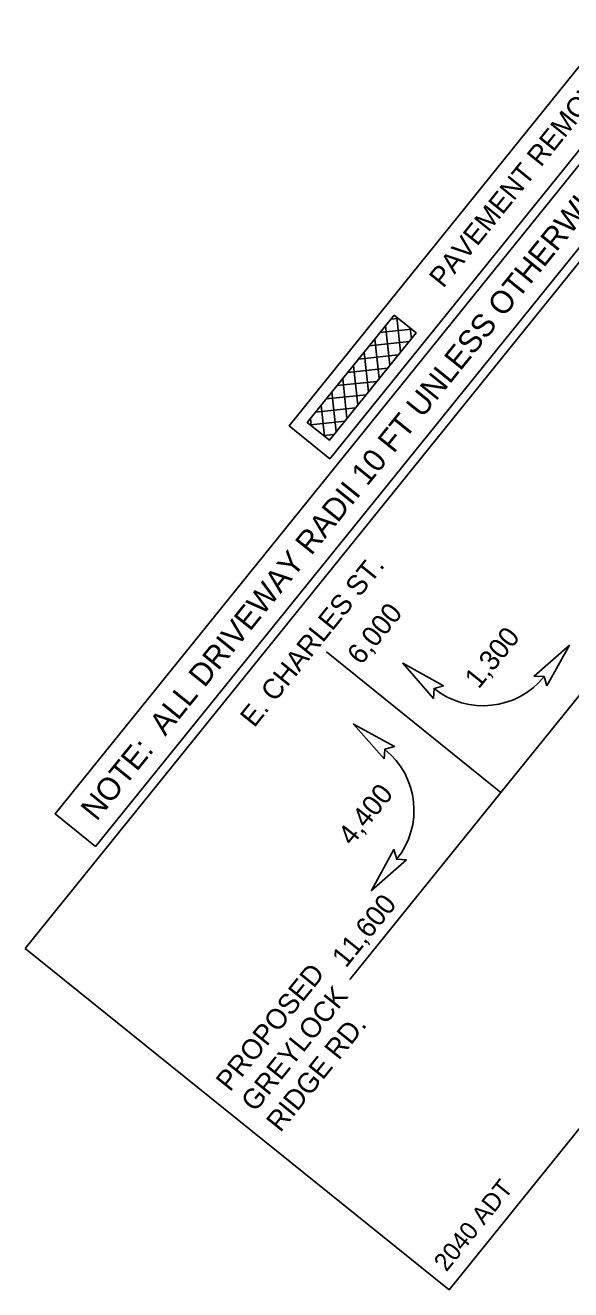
# Model space of a CAD drawing. Extents: x 1487832 to 1490056, y 498345 to 500343.
# Drawn here: x 1489252.4 to 1489387.8, y 499624 to 499938.3 of the extents above; entities that cross this region are included whole.
import ezdxf

# ---------------------------------------------------------------- set-up
doc = ezdxf.new("R2010")
doc.units = 0
for name, color, linetype in [('Prop DSN Text', 7, 'Continuous'), ('Prop Grid Mask', 7, 'Continuous'), ('Prop Hatching', 7, 'Continuous'), ('Prop Horizontal Alignment Curve and Spiral Data', 7, 'Continuous')]:
    doc.layers.add(name, color=color, linetype=linetype)

msp = doc.modelspace()

# ---------------------------------------------------------------- linework, layer by layer
at = {"layer": 'Prop DSN Text'}
for p in [(1489407.93, 499794.07), (1489327.11, 499782.51), (1489332.93, 499701.07)]:
    msp.add_line(p, (1489370.43, 499747.57), dxfattribs=at)
for points in [[(1489381.83, 499774.06), (1489387.45, 499784.16), (1489378.68, 499776.51), (1489381.17, 499776.38)], [(1489356.15, 499774.1), (1489346.05, 499779.72), (1489353.69, 499770.96), (1489353.83, 499773.45)], [(1489341.48, 499755.91), (1489333.84, 499764.59), (1489344.03, 499758.97), (1489341.63, 499758.31)], [(1489346.96, 499730.82), (1489338.28, 499723.19), (1489343.89, 499733.37), (1489344.56, 499730.97)]]:
    msp.add_lwpolyline(points, close=True, dxfattribs=at)
for centre, start, end in [((1489366.04, 499788.58), 231.1156, 321.1156), ((1489329.42, 499743.17), 321.1156, 51.1156)]:
    msp.add_arc(centre, 19.44, start, end, dxfattribs=at)
at = {"layer": 'Prop Grid Mask'}
for points in [[(1489328, 499830.53), (1489408.29, 499930.09), (1489398.12, 499938.29), (1489317.83, 499838.73)], [(1489269.83, 499734.17), (1489420.13, 499920.54), (1489410.09, 499928.63), (1489259.79, 499742.26)], [(1489252.37, 499708.83), (1489421.93, 499919.09), (1489527.15, 499834.24), (1489357.58, 499623.98)], [(1489343.91, 499866.27), (1489322.37, 499839.56), (1489327.85, 499835.14), (1489349.39, 499861.85)]]:
    msp.add_lwpolyline(points, close=True, dxfattribs=at)
at = {"layer": 'Prop Hatching'}
for p, q in [((1489340.4, 499861.92), (1489348.26, 499862.76)), ((1489342.87, 499853.77), (1489341.81, 499863.67)), ((1489343.06, 499865.22), (1489344.96, 499865.42)), ((1489345.54, 499857.08), (1489344.61, 499865.7)), ((1489348.2, 499860.38), (1489347.91, 499863.04)), ((1489337.73, 499858.61), (1489347.63, 499859.67)), ((1489340.21, 499850.47), (1489339.15, 499860.37)), ((1489335.07, 499855.31), (1489344.97, 499856.37)), ((1489337.54, 499847.17), (1489336.48, 499857.06)), ((1489334.88, 499843.86), (1489333.82, 499853.76)), ((1489332.22, 499840.56), (1489331.16, 499850.46)), ((1489332.41, 499852.01), (1489342.3, 499853.07)), ((1489329.55, 499837.26), (1489328.49, 499847.16)), ((1489329.74, 499848.71), (1489339.64, 499849.77)), ((1489326.66, 499836.09), (1489325.83, 499843.85)), ((1489327.08, 499845.4), (1489336.98, 499846.46)), ((1489324.42, 499842.1), (1489334.31, 499843.16)), ((1489323.13, 499838.94), (1489331.65, 499839.86)), ((1489323.36, 499838.76), (1489323.17, 499840.55)), ((1489326.43, 499836.28), (1489328.99, 499836.55))]:
    msp.add_line(p, q, dxfattribs=at)

# ---------------------------------------------------------------- texts
at = {"layer": 'Prop DSN Text'}
for s, height, rotation, p in [('PAVEMENT REMOVAL', 5, 51.1157, (1489356.12, 499872.76)), ('E. CHARLES ST.', 5, 51.1156, (1489309.18, 499763.51)), ('6,000', 5, 51.1156, (1489335.74, 499779.06)), ('1,300', 5, 51.1156, (1489364.91, 499773.11)), ('4,400', 5, 51.1156, (1489333.46, 499734.11)), ('11,600', 5, 51.1156, (1489331.95, 499703.78)), ('PROPOSED', 5, 51.1156, (1489303.17, 499672.98)), ('GREYLOCK', 5, 51.1156, (1489309.42, 499667.94)), ('RIDGE RD.', 5, 51.1156, (1489315.68, 499662.89)), ('2040 ADT', 4.444, 51.121, (1489356.89, 499628.24))]:
    msp.add_text(s, height=height, rotation=rotation, dxfattribs=at).set_placement(p)
at = {"layer": 'Prop Horizontal Alignment Curve and Spiral Data'}
msp.add_text('NOTE:  ALL DRIVEWAY RADII 10 FT UNLESS OTHERWISE NOTED.', height=5.625, rotation=51.1156, dxfattribs=at).set_placement((1489270.06, 499740.24))

doc.saveas('drawing.dxf')
